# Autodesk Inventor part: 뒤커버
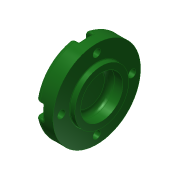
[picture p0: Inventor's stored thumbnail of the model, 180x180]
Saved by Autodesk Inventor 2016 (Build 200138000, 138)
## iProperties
Created: 2015-11
Part Number: 뒤커버
Material: 알루미늄 6061
Document SubType Name: Modeling
Designer: mduedu
Density: 1 g/cm^3
Appearance: 매끄러움 - 짙은 산림 녹색
Author: mduedu
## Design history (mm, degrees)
sketch "스케치1"
  geometry: L1 (-7, 0)-(7, 0); L2 (-7, 0)-(-7, 26); L3 (-7, 26)-(4, 26); L4 (4, 26)-(4, 16); L5 (4, 16)-(7, 16); L6 (7, 16)-(7, 0); 2 further points
  constraints: 12 end point, 3 perpendicular, 2 parallel, 1 coincident, 1 horizontal, 1 midpoint
  dimensions: "d0" = 14 distance of L1.start L1.end; "d1" = 52 diameter of L3 L1; "d2" = 3 distance of L4.end L5.end; "d3" = 32 diameter of L5 L1
revolve "회전1" sketch "스케치1" stored, may be unused: angle "d4" = 90 deg
hole "구멍1" diameter "d7" = 25; stored, may be unused: countersink angle "d11" = 90 deg, drill point angle "d13" = 0 deg; dims "d8" = 6, "d9" = 4, "d10" = 2, "d12" = 8, "d62" = 10, "d63" = 10
fillet "모깎기2" dims "d36" = 3
fillet "모깎기3" dims "d37" = 3
fillet "모깎기4" dims "d38" = 0.3
sketch "스케치3" dims "d61" = 42
  geometry: C1 r 26 at (0, 0) reference; 2 further points
  constraints: 2 vertical alignment, 1 coincident, 2 other
hole "구멍4" sketch "스케치3" at (0, -21) diameter "d44" = 4.5; stored, may be unused: countersink angle "d48" = 90 deg, drill point angle "d50" = 0 deg; dims "d45" = 6, "d46" = 8, "d47" = 4.6, "d49" = 8
sketch "스케치4"
  geometry: L1 (-4, 0)-(-4, -4.69); L2 (4, 0)-(4, -4.69); A1 r 4 centre (0, 0) between (3.614, -1.714) and (-3.614, -1.714) reference; A2 r 26 centre (0, 21) between (-4, -4.69) and (4, -4.69) reference; 1 further point
  constraints: 4 end point, 4 point on circle, 2 tangent, 1 parallel, 1 vertical
extrude "돌출1" cut sketch "스케치4" stored distance "d51" = 0; taper "d52" = 0 deg
fillet "모깎기5" dims "d56" = 0.3
fillet "모깎기6" dims "d57" = 1
node "솔리드1"
pattern_circular "원형 패턴1" dims angle "d54" = 360 deg
